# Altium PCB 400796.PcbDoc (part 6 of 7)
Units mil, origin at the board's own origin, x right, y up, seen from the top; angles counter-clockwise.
Board outline 2086.61 x 2086.61 mil, 6 copper layers (Top Layer, Mid Layer 1, Mid Layer 2, Mid Layer 3, Mid Layer 4, Bottom Layer), stack 58.818 mil thick; 313 components, 234 nets, 1244 pads, 2538 vias.
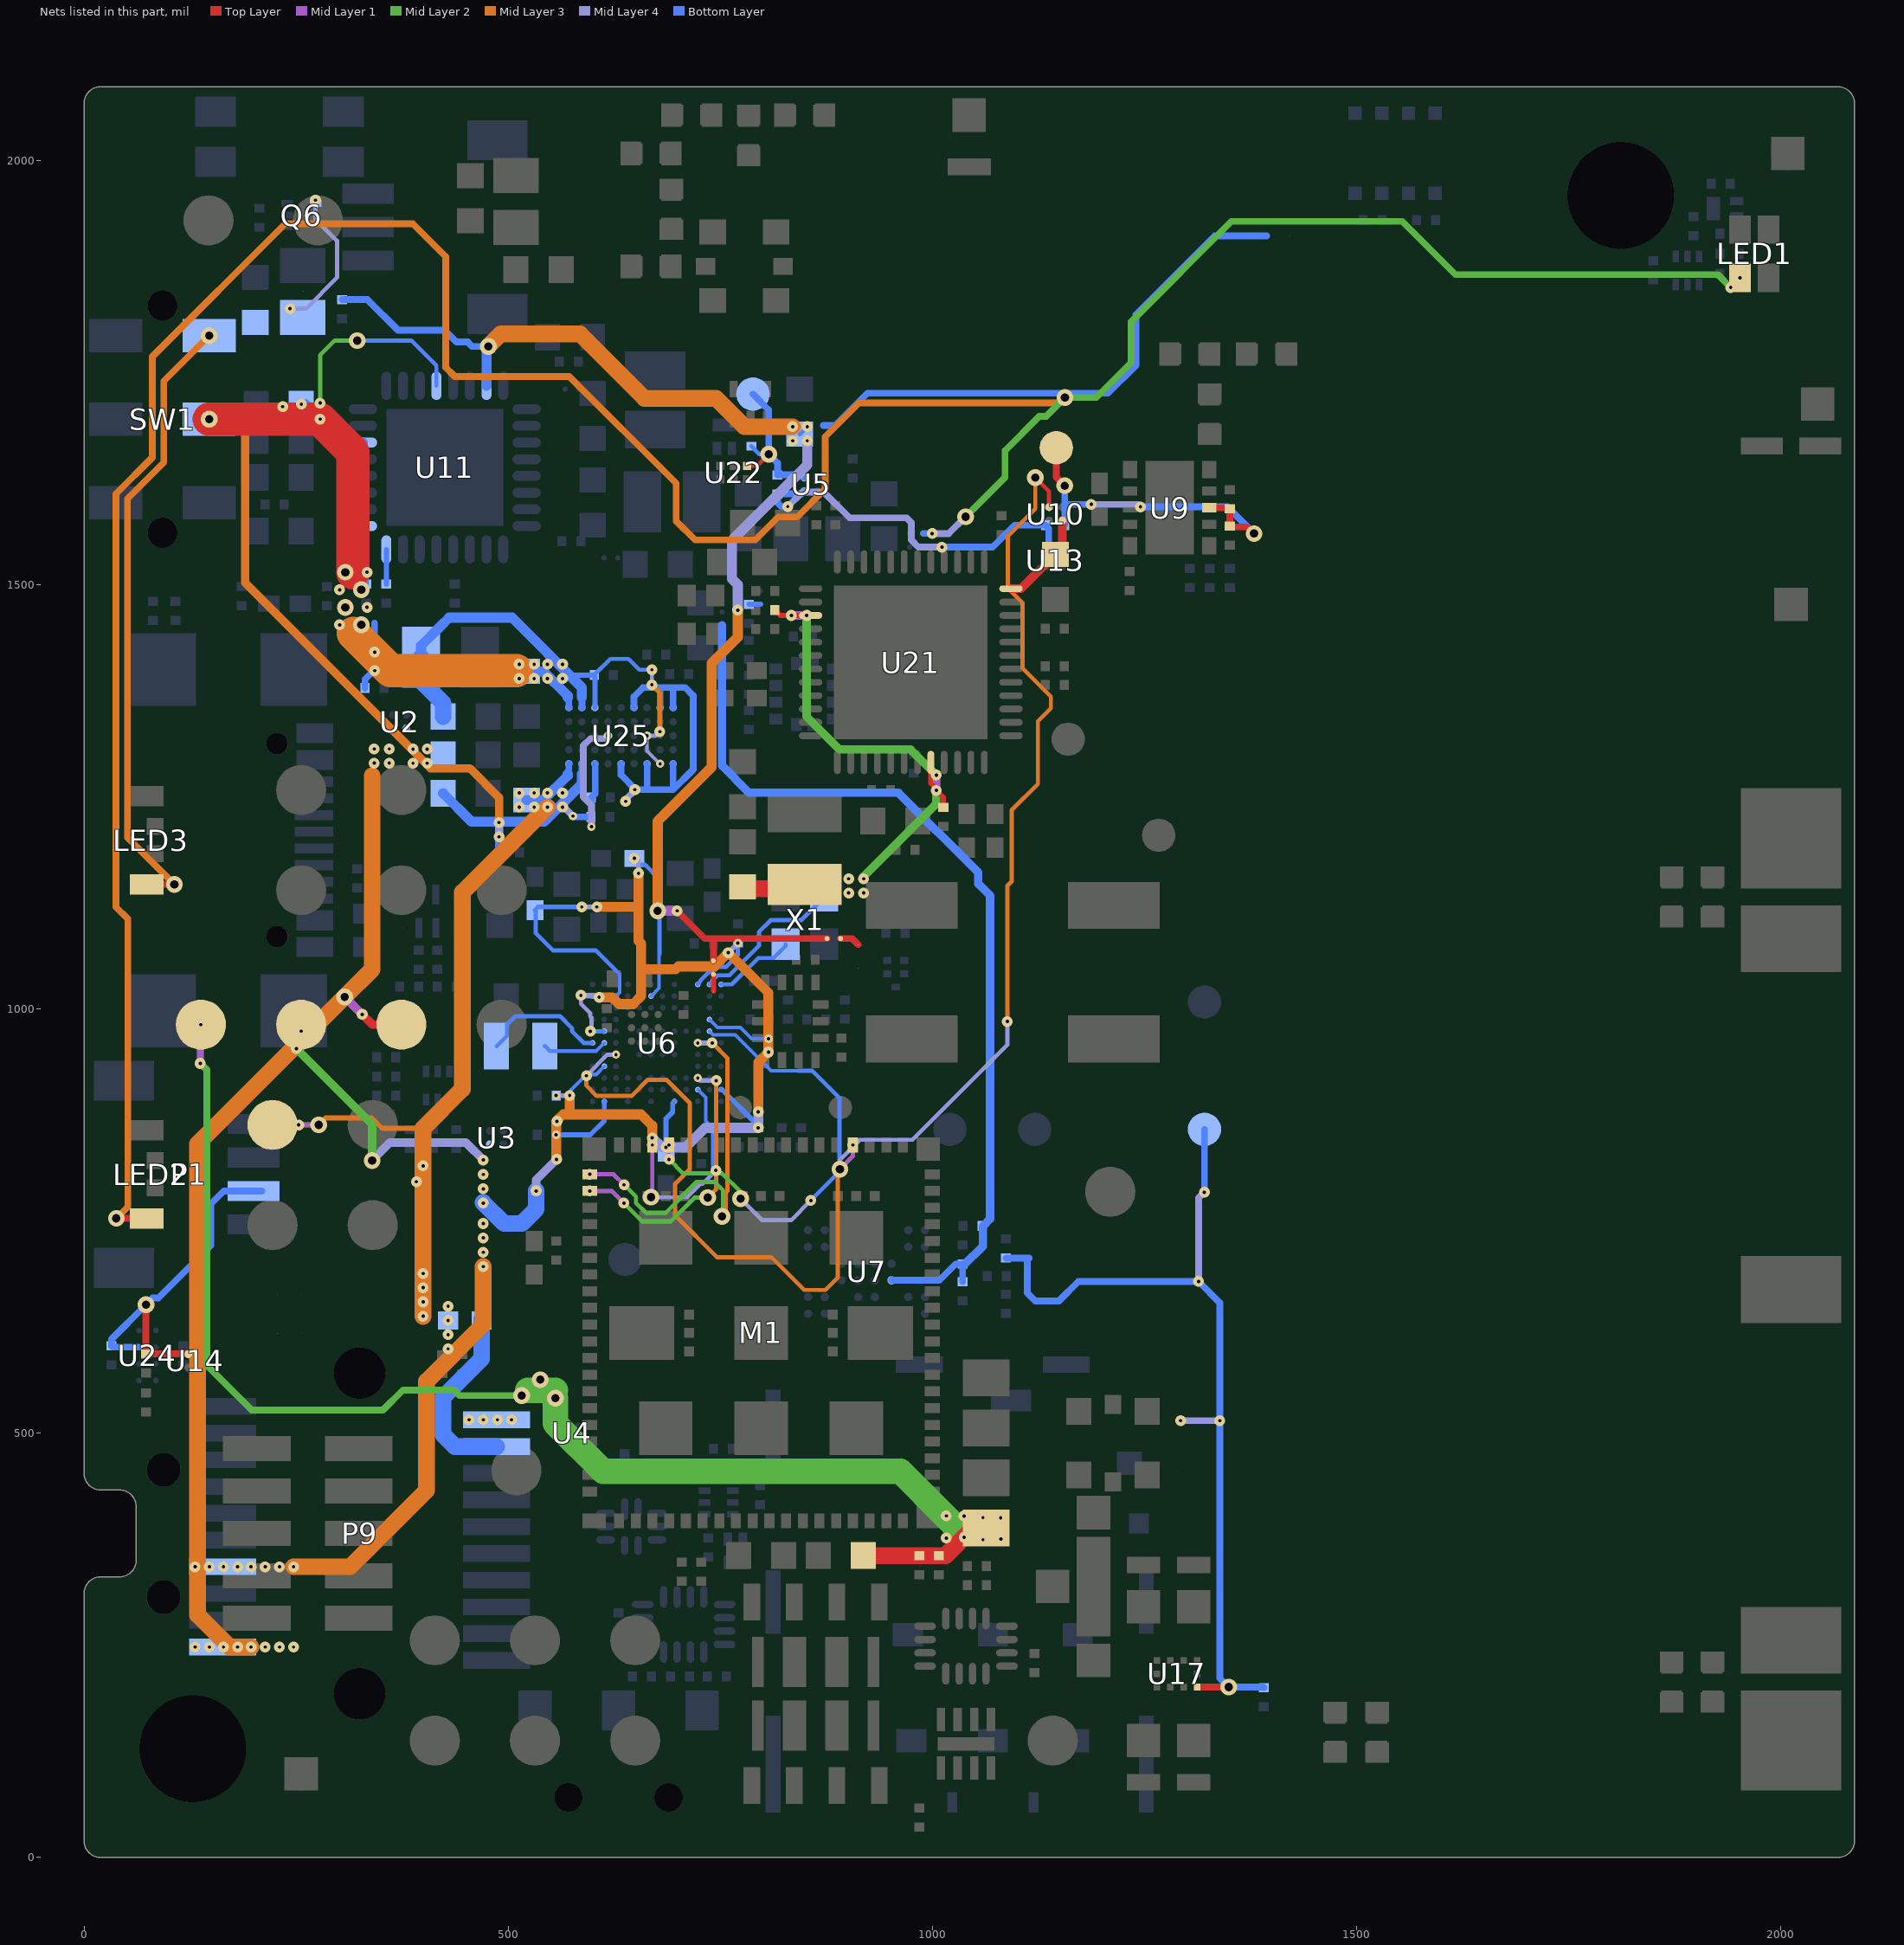
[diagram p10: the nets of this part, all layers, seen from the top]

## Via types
v1: diameter 12.8, hole 3.94, Mid Layer 4 to Bottom Layer, tented both sides, 653 vias
v2: diameter 12.8, hole 3.94, Top Layer to Mid Layer 1, tented both sides, 560 vias
v3: diameter 12.8, hole 3.94, Mid Layer 3 to Mid Layer 4, tented both sides, 388 vias
v4: diameter 19.68, hole 9.84, Mid Layer 1 to Mid Layer 4, tented both sides, 311 vias
v5: diameter 12.8, hole 3.94, Mid Layer 1 to Mid Layer 2, tented both sides, 265 vias
v6: diameter 19.68, hole 9.84, Top Layer to Bottom Layer, tented both sides, 169 vias
v7: diameter 9.84, hole 3.94, Mid Layer 4 to Bottom Layer, tented both sides, 105 vias
v8: diameter 12.8, hole 3.94, Top Layer to Mid Layer 1, tented top, 70 vias
v9: diameter 9.84, hole 3.94, Top Layer to Mid Layer 1, tented both sides, 17 vias

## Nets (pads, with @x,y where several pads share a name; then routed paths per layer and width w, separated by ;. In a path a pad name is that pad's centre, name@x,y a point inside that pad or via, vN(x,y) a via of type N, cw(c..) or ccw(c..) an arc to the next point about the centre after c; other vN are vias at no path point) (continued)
VBUSOUT: C50.2 R10.1 U11.22 | length 817.3
  Mid Layer 3 w9.84: v3@230.08,1709.58 214.8,1709.58 189.96,1684.75 189.96,1531.64 189.95,1501.98 408.46,1283.46 454.72,1283.46 489.17,1249.02 v3(489.17,1219.49)
  Mid Layer 4 w9.84: v3(234.08,1709.58) 253.14,1709.58 v1(256.16,1712.6) ; v1(489.17,1202.76) v3(489.17,1219.49)
  Bottom Layer w9.84: v1(489.17,1202.76) 489.17,1185.81 R10.1@490.73,1184.25
  Bottom Layer w11.81: v1(256.16,1712.6) 260.51,1712.6 282.44,1690.67 305.79,1667.32 U11.22@328.74,1667.32
VCOM0.RXD: M1.57 U6.K3 | length 261
  Mid Layer 1 w4.92: v4(668.34,778.09) 669.8,779.56 v2(669.8,839.57)
  Mid Layer 4 w4.92: v4@665.34,784.09 671.51,777.92 710.43,777.92 726.29,793.79 728.81,793.79 v1(744.68,809.66)
  Bottom Layer w4.13: U6.K3@723.41,904.72 732.87,895.26 732.87,867.69 741.56,859
  Bottom Layer w4.92: 741.56,859 741.56,812.78 v1(744.68,809.66)
VCOM0.TXD: M1.56 U6.E2 | length 549.9
  Mid Layer 1 w4.92: v5(689.49,822.64) v2(689.49,839.57)
  Mid Layer 2 w4.92: v5(689.49,822.64) 705.97,806.16 751.95,806.16 773.75,784.36 v4(773.75,776.36)
  Mid Layer 4 w4.92: v4(773.75,776.36) 799.13,750.98 833.46,750.98 v1(856.6,774.12) v1@857.6,775.12
  Bottom Layer w4.13: U6.E2@737.19,973.62 741.42,969.39 767.59,969.39 809.96,927.02 842,927.02
  Bottom Layer w4.92: 842,927.02 858.34,927.02 890.27,895.09 890.27,807.8 v1(856.6,774.12)
VCOM1.RXD: M1.62 U6.J3 | length 330.7
  Mid Layer 1 w4.92: v2(595.98,785.43) 621.98,785.43 v5(636.36,771.06)
  Mid Layer 2 w4.92: v5(636.36,771.06) 657.91,749.51 691.41,749.51 719.57,777.66 v4(735.14,777.66)
  Mid Layer 3 w4.92: v4(735.14,777.66) 745.16,787.68 745.16,859 v3(745.16,915.5)
  Mid Layer 4 w5.91: v7(723.41,918.5) 726.41,915.5 v3(745.16,915.5)
VCOM1.TXD: M1.61 U6.F3 | length 462
  Mid Layer 1 w4.92: v2(595.98,805.12) 624.11,805.12 v5(636.49,792.74)
  Mid Layer 2 w4.92: v5(636.49,792.74) 650.36,778.87 650.36,771.41 661.88,759.89 685.97,759.89 715.94,789.86 722.08,796 743.4,796 749.58,789.83 752.87,786.53 752.87,756.36 v4(751.83,755.32)
  Mid Layer 3 w5: v3(740.38,959.84) 758.21,942 758.21,785.44 756.48,783.7 756.48,759.97 v4(751.83,755.32)
  Mid Layer 4 w5.91: v7(723.41,959.84) v3(740.38,959.84)
VDD_ACC: R26.1 ST7.2 | length 13.9
  Bottom Layer w6: R26.1@783.46,1476.77 ST7.2@797.35,1476.77
VDD_BMI270: SB4.1 ST1.2 | length 23.6
  Top Layer w8: ST1.2@891.65,1082.91 905.13,1082.91 SB4.1@912.32,1075.72
VDD_BMM350: SB10.1 ST4.2 | length 19.9
  Top Layer w6: SB10.1@741.78,1020.8 ST4.2@741.78,1040.69
VDD_BUCK: C60.2 C65.2 C70.2 L6.2 U21.15 U21.32 | length 669.2
  Top Layer w6: C70.2@814.17,1469.99 814.17,1469.4 816.49,1467.09 817.08,1467.09 820.58,1463.58 v2(833.66,1463.58) U21.15@856.3,1463.58 ; U21.32@998.03,1290.35 998.03,1265.87 1004.45,1259.45 v2(1004.45,1257.48) 1012.8,1249.13 C60.2@1012.8,1237.6
  Top Layer w20: C65.2@780.7,1141.46 L6.2@824.47,1141.46 ; L6.2@829.72,1146.71 L6.2@824.47,1141.46 ; L6.2@844.16,1141.46 L6.2@824.47,1141.46
  Mid Layer 1 w9.84: v2(833.66,1463.58) v5(851.66,1463.58) ; v2(1004.45,1257.48) v5(1004.45,1275.48)
  Mid Layer 2 w9.84: v5(851.66,1463.58) 851.66,1344.32 890.28,1305.71 974.22,1305.71 v5(1004.45,1275.48) 1004.45,1241.73 918.82,1156.1 v5(918.82,1153.23)
  other v2: 901.1,1136.5 901.1,1153.23
  other v5: 918.82,1136.5
VDD_ENV: SB5.1 ST5.2 | length 650
  Bottom Layer w7.87: ST5.2@871.19,1687.36 885.19,1687.36 923.23,1725.39 1206.69,1725.39 1239.67,1758.37 1239.67,1817.96 1332.63,1910.93 SB5.1@1393.71,1910.93
VDD_EXP_BRD: C76.2 P1.2 R5.1 U14.A1 U24.B2 | length 424.5
  Top Layer w8: v6(72.97,651.36) R5.1@72.97,593.4 122.42,593.4 U14.A1@122.46,593.44
  Bottom Layer w8: U24.B2@64.96,601.38 33.86,601.38 C76.2@32.48,602.76 32.48,610.86 v6@71.44,649.83 ; v6(72.97,651.36) 80.76,659.15 87.51,659.15 149.67,721.31 149.67,770.16 164.94,785.43 P1.2@209.65,785.43
VDD_LED: LED1.4 LED2.4 ST2.2 | length 3781.9
  Top Layer w7.87: v6(38.09,753.11) LED2.4@73.74,753.12
  Mid Layer 1 w5.91: v5(1940.64,1850.08) v2(1951.77,1861.22)
  Mid Layer 2 w7.87: v4(1039.1,1579.89) 1085.48,1626.28 1085.48,1657.81 1125.8,1698.12 1133.75,1698.12 v4(1156.09,1720.46) 1192.95,1720.46 1233.82,1761.33 1233.82,1809.38 1352.31,1927.87 1553.74,1927.87 1616.53,1865.08 1925.64,1865.08 v5(1940.64,1850.08)
  Mid Layer 3 w7.87: v6(38.09,753.11) 51.7,766.71 51.7,1106.06 37.56,1120.2 37.56,1606.79 80.54,1649.77 80.54,1768.57 237.16,1925.2 387.45,1925.2 426.18,1886.46 426.18,1755.91 437.01,1745.08 571.98,1745.08 697.83,1619.22 697.83,1574.8 720.17,1552.47 791.1,1552.47 818.35,1579.73 840.64,1579.73 873.44,1612.52 873.44,1673.99 913.52,1714.07 1149.7,1714.07 v4(1156.09,1720.46)
  Mid Layer 4 w7.87: v1(999.6,1560.04) 1019.25,1560.04 v4(1039.1,1579.89)
  Bottom Layer w7.87: ST2.2@989.03,1560.17 999.47,1560.17 v1(999.6,1560.04)
VDD_MEM: C37.2 R43.2 R50.2 ST9.2 U7.C3 | length 1114
  Bottom Layer w7.87: U7.C3@951.77,680.12 1007.87,680.12 1027.16,699.41 C37.2@1035.43,699.41 R50.2@1035.43,678.54
  Bottom Layer w9.84: ST9.2@751.97,1451.77 ST9.2@751.97,1451.65 751.97,1286.42 783.73,1254.65 959.87,1254.65 1053.94,1160.59 1053.94,1147.43 1067.91,1133.45 1067.91,752.56 1059.45,744.09 1059.45,720.37 C37.2@1036.44,697.37
VDD_nRF53: C12.1 C13.1 C15.1 C16.1 C19.1 C20.1 C21.1 C22.2 P9.4 TP2.1 U3.A1 U6.A3 U6.B7 U6.B10 U6.B12 U6.D2 U6.E11 U6.H11 U6.K1 U6.L5 U6.L11 | length 2954.3
  Top Layer w5.91: v2(255.84,973.76) 255.91,973.82 TP2.1@255.91,981.39
  Mid Layer 1 w5.91: v5(250.31,953.22) 255.84,958.76 v2(255.84,973.76)
  Mid Layer 2 w10: v5(250.31,953.22) 339.54,864 v4(339.54,821.38)
  Mid Layer 3 w11.81: v3@556.48,823.04 556.48,867.52 564.55,875.59 656.39,875.59 669.61,862.37 v3(669.61,847.92) ; 572.42,875.98 v3(572.42,897.83) ; v3(604.33,1120.08) 653.53,1120.09 ; v3(607.08,1013.63) 622.45,1013.63 630.47,1005.61 647.07,1005.61 656.53,1015.06 656.53,1046.56 ; v3(653.53,1159.65) 653.53,1120.09 ; v3(794.64,878.78) 794.64,936.98 v3(806.68,949.02) 806.68,1018.87 v3(759.32,1066.23) 743.07,1049.98 700.47,1049.98 697.05,1046.56 656.53,1046.56 ; 653.53,1120.09 653.53,1080.03 656.53,1077.03 656.53,1046.56
  Mid Layer 3 w19.68: v3(247.05,342.52) 313.73,342.52 403.54,432.34 403.54,561.02 470.47,627.95 v3(470.47,696.25)
  Mid Layer 4 w4.92: v1(585.61,1015.95) 585.61,1005.9 596.71,994.8 596.71,991.62 597.24,991.09 597.24,990.8 597.55,990.49 597.55,989.21 598.08,988.69 598.08,974.9 v1(596.79,973.62)
  Mid Layer 4 w5.91: v7(556.48,851.58) v3@556.48,867.32 ; v7(556.48,897.83) v3@572.23,897.83 ; v1(585.61,1015.95) 604.77,1015.95 v3(607.08,1013.63) ; v1(586.61,1120.08) v3(604.33,1120.08) ; v3(653.53,1159.65) v1@653.53,1175.39 ; v3@759.52,1066.42 v7(770.65,1077.56) ; v3(806.68,949.02) v7(806.68,964.76)
  Mid Layer 4 w10: v4(339.54,821.38) 360.5,842.34 449.98,842.34 v1(470.47,821.85) ; v1(532.84,785.4) 532.84,798.61 546.08,811.84 v3(556.88,822.64)
  Mid Layer 4 w11.81: v3(669.61,847.92) 669.97,847.92 681.01,836.89 v1(686.01,836.89)
  Mid Layer 4 w12: v1(686.01,836.89) 709.3,836.89 732.25,859.84 v1(794.64,859.84) v3(794.64,878.78)
  Bottom Layer w4.13: C20.1@557,897.83 567.31,897.83 592.01,922.54 599.19,922.54 599.39,922.74 603.62,922.74 U6.H11@613.17,932.28 ; 626.76,1045.28 631.18,1040.85 631.18,1019.19 U6.B10@626.95,1014.96 ; U6.B7@668.29,1014.96 677.84,1024.51 677.84,1064.94 ; U6.D2@737.19,987.4 746.73,977.85 773.6,977.85 786.62,964.84 C12.1@805.96,964.84
  Bottom Layer w4.92: C22.2@531.48,1116.34 C22.2@535.22,1120.08 ; C22.2@532.46,1116.34 532.46,1089.17 552.71,1068.92 603.12,1068.92 626.76,1045.28 ; v7(556.48,897.83) C20.1@557,897.83 ; v1(596.79,973.62) U6.E11@613.17,973.62 ; v1(648.6,1177.36) 655.99,1169.98 660.91,1169.98 678.13,1152.76 678.13,1063.98 ; U6.A3@723.41,1028.74 723.41,1029.22 726.46,1032.27 726.46,1033.32 742.45,1049.31 756.61,1049.31 770.65,1063.35 C21.1@770.65,1073.62
  Bottom Layer w5.91: C22.2@535.22,1120.08 v1(586.61,1120.08) ; v7(556.48,851.58) 596.74,851.58 613.17,868 U6.L11@613.17,890.95 ; v1(585.61,1015.95) 586.6,1014.96 U6.B12@599.39,1014.96 ; v1(686.01,836.89) 686.01,870.63 693.82,878.44 693.82,888.92 U6.L5@695.85,890.95 ; U6.K1@750.97,904.72 751.12,904.57 752.09,904.57 C13.1@794.64,862.03
  Bottom Layer w19.68: v1@470.47,771.65 495.08,747.04 515.92,747.04 532.84,763.97 v1(532.84,785.4)
  other v1: 130.9,342.52 147.64,342.52 164.37,342.52 181.1,342.52 470.47,771.06 470.47,787.99 470.47,804.92
  other v3: 196.85,342.52 213.58,342.52 230.32,342.52 470.47,713.18 470.47,730.11 470.47,747.04 557.48,867.52
VDD_nRF91: C1.1 C2.1 C3.1 FB1.1 P9.11 TP3.1 U4.A1 | length 1555.2
  Top Layer w20: FB1.1@918.57,355.52 C2.1@1007.35,355.52 ; C2.1@1007.22,355.62 1015.38,355.62 1048.16,388.4 C3.1@1063.24,388.4
  Mid Layer 1 w8: v5(137.07,935.72) 137.07,980.66 v2(137.8,981.39)
  Mid Layer 2 w8: v5(137.07,935.72) 144.7,928.08 144.7,579.98 197.49,527.19 352.36,527.19 376.02,550.84 435.78,550.84 442.28,544.34 v4(515.7,544.34)
  Mid Layer 2 w30: v4@522.95,550.34 v4@555.47,550.34 ; v4(555.47,541.34) 555.47,511.53 611.94,455.06 962.06,455.06 1015.44,401.68 1028.71,388.41
  other v1: 453.74,515.75 470.47,515.75 487.21,515.75 503.94,515.75
  other v2: 1059.47,374.43 1080.55,375.35 1059.47,400.55 1080.39,400.42
  other v4: 537.59,563.02
  other v5: 1016.26,376.37 1037.34,377.29 1016.26,402.49 1037.18,402.36
VDD_nRF91_RES: P9.12 R24.1 U4.A2 | length 223.8
  Bottom Layer w19.68: R24.1@468.51,634.37 468.51,587.6 423.23,542.32 423.23,498.03 437.01,484.25 P9.12@486.22,484.25
VDD_RF_FE_3V3: C32.2 C33.2 R56.1 TP8.1 U9.3 U13.A1 | length 428.2
  Top Layer w7.87: TP8.1@1145.87,1661.19 1145.87,1626.52 v6(1155.91,1616.49) ; U9.3@1326.28,1590.55 1343.81,1590.55 ; C32.2@1350.39,1583.97 1350.39,1567.91 1371.06,1567.91 v6(1378.94,1560.04)
  Mid Layer 4 w7.87: v1(1187.01,1594.49) 1242.13,1594.49 v1(1245.08,1591.54)
  Bottom Layer w7.87: U13.A1@1152.56,1536.55 R56.1@1152.56,1566.66 ; R56.1@1155.91,1570.01 1155.91,1594.49 ; v6(1155.91,1616.49) 1155.91,1594.49 ; v1(1187.01,1594.49) 1155.91,1594.49 ; v1(1245.08,1591.54) 1347.44,1591.54 v6(1378.94,1560.04)
VDD_RF_FE_3V3_SP: R25.2 R56.2 ST3.2 U5.A2 U13.A2 | length 474.7
  Mid Layer 4 w7.87: v1(829.47,1591.77) 846.68,1608.97 871.87,1608.97 902.27,1578.58 969.45,1578.58 975.03,1573 975.03,1552.48 983.44,1544.07 v1(1011.13,1544.07)
  Bottom Layer w7.87: v1(829.47,1591.77) 822.03,1591.77 817.36,1596.43 R25.2@817.36,1606.83 845.51,1606.83 U5.A2@848.86,1610.18 ; ST3.2@989.03,1544.07 v1(1011.13,1544.07) 1070.64,1544.07 1096.58,1570.01 R56.2@1133.46,1570.01 ; R56.2@1133.17,1570.01 R56.2@1133.32,1569.87 ; R56.2@1133.46,1569.42 1136.81,1566.07 U13.A2@1136.81,1536.55
VDD_RF_FE_SR: R25.1 R62.1 TP11.1 U5.A1 U22.4 | length 195.9
  Top Layer w4.92: U22.4@781.5,1639.76 793.31,1639.76 v6(807.09,1653.54)
  Bottom Layer w4.92: R62.1@786.42,1662.99 795.87,1653.54 v6(807.09,1653.54)
  Bottom Layer w7.87: TP11.1@788.39,1724.41 807.09,1705.71 v6(807.09,1653.54) 817.36,1643.27 R25.1@817.36,1629.27 845.51,1629.27 U5.A1@848.86,1625.93
VDD_SENS: C90.2 R30.2 ST1.1 ST4.1 ST5.1 U11.31 | length 1556
  Top Layer w8: v2(698.94,1115.44) 731.47,1082.91 741.96,1082.91 ; ST4.1@741.78,1056.69 741.78,1082.74 741.96,1082.91 ; ST1.1@875.65,1082.91 741.96,1082.91
  Mid Layer 1 w12: v4(676.08,1115.44) v2(698.94,1115.44)
  Mid Layer 3 w12: v4(676.08,1115.44) 676.08,1221.09 739.66,1284.67 739.66,1407.26 770.44,1438.04 v3(770.44,1469.78)
  Mid Layer 3 w19.68: v6(476.38,1780.51) 491.14,1795.28 584.65,1795.28 660.59,1719.33 745.01,1719.33 778.32,1686.02 v3(835.17,1686.02)
  Mid Layer 4 w4.92: v1(835.17,1669.29) v3(835.17,1686.02)
  Mid Layer 4 w12: v3(770.44,1469.78) 770.44,1499.9 763.68,1506.66 763.68,1552.02 852.36,1640.7 v1(852.36,1669.29)
  Bottom Layer w4.92: C90.2@843.5,1677.17 853.69,1687.36 ST5.1@855.19,1687.36
  Bottom Layer w8: R30.2@304.16,1835.77 334.06,1835.77 370.13,1799.7 424.99,1799.7 438.95,1785.73 452.26,1785.73 457.48,1780.51 v6@474.41,1780.51
  Bottom Layer w11.81: U11.31@474.41,1734.25 474.41,1780.51 v6(476.38,1780.51)
  other v3: 852.36,1686.02
VDDIO_CTRL: M1.45 U6.G10 U10.B2 | length 1770.2
  Top Layer w4.92: v6(1121.06,1625.98) 1137.32,1609.72 U10.B2@1137.32,1591.14
  Mid Layer 1 w4.92: v4(890.91,811.19) 906.02,826.31 v2(906.02,839.57)
  Mid Layer 3 w4.92: v3(592.08,921.24) 592.08,909.59 604.21,897.45 645.43,897.45 664.36,916.38 686.66,916.38 713.93,889.11 713.93,810.93 696.58,793.58 696.58,756.76 746.16,707.18 810.49,707.18 848.91,668.76 873.87,668.76 888.45,683.34 888.45,808.74 v4(890.91,811.19) ; v3(1088.08,985.15) 1088.08,1144.86 1093.34,1150.11 1093.34,1234.23 1124.21,1265.1 1124.21,1338.99 1139.45,1354.22 1139.45,1367.83 1106.19,1401.09 1106.19,1478.25 1088.86,1495.59 1088.86,1557.28 1121.06,1589.48 v6(1121.06,1625.98)
  Mid Layer 4 w4.92: v3(592.08,921.24) 616.9,946.06 v7(626.95,946.06) ; v4(890.91,811.19) 890.91,822.33 914.37,845.78 976.51,845.78 1088.08,957.36 v3(1088.08,985.15)
VDDIO_nRF70: C30.2 U10.A1 U21.48 | length 111.9
  Top Layer w10: U21.48@1092.52,1495.08 1104.33,1495.08 C30.2@1144.68,1535.43 C30.2@1152.09,1542.83 ; C30.2@1153.07,1542.83 U10.A1@1153.07,1575.39
VIO: C38.2 R29.2 SB1.1 TP21.1 U17.4 | length 1080.7
  Top Layer w7.87: U17.4@1311.75,200.77 v6(1349.15,200.77)
  Mid Layer 4 w7.87: v1(1292.32,514.76) v1(1338.58,514.76) ; v1@1313.55,679.76 1313.55,777.1 v1(1320.36,783.91)
  Bottom Layer w7.87: R29.2@1086.61,706.3 1113.91,706.3 ; 1111.71,704.11 1111.71,665.16 1121.12,655.76 1148.95,655.76 1171.95,678.76 v1(1313.55,678.76) 1338.58,653.73 v1(1338.58,514.76) 1338.58,211.34 v6(1349.15,200.77) 1389.97,200.77 C38.2@1390.57,200.18 ; v1(1320.36,783.91) 1320.47,784.02 TP21.1@1320.47,858.07
VOUT_BUCK0: C78.2 C82.1 L9.2 U25.B1 U25.C3 U25.G5 U25.H5 | length 634
  Mid Layer 3 w5.91: v3(669.29,1381.89) 678.6,1372.58 v3(678.6,1326.59)
  Mid Layer 4 w4.13: v7(663.58,1321.85) 663.58,1304.13 v7(678.94,1288.78)
  Mid Layer 4 w4.92: v7(663.58,1321.85) 673.87,1321.85 v3(678.6,1326.59) ; v3(669.29,1381.89) v1(669.29,1399.61)
  Bottom Layer w4.92: C82.1@599.41,1393.31 601.23,1393.31 620.32,1412.4 641.73,1412.4 654.53,1399.61 v1(669.29,1399.61)
  Bottom Layer w5.91: 573.22,1393.31 C82.1@599.41,1393.31 ; U25.G5@602.17,1354.92 C82.1@602.17,1390.98
  Bottom Layer w7.87: U25.H5@586.81,1354.92 586.81,1366.93
  Bottom Layer w11.81: L9.2@397.24,1414.37 397.24,1427.95 419.49,1450.2 430.32,1461.02 504.53,1461.02 586.81,1378.74 586.81,1366.93
  Bottom Layer w19.68: L9.2@397.24,1414.37 397.24,1386.22 423.23,1360.24 C78.2@423.23,1344.49
VOUT_BUCK3: C81.2 L10.2 P9.1 TP14.1 U2.A2 U25.H1 | length 1452.8
  Top Layer w10: v2(327.86,993.41) 328.04,993.41 340.06,981.39 TP14.1@374.02,981.39
  Mid Layer 1 w10: v4(307.05,1014) 307.27,1014 v2(327.86,993.41)
  Mid Layer 3 w19.68: v3(196.85,248.03) 171.71,248.03 133.86,285.89 133.86,840.8 v4(307.05,1014) 339.57,1046.51 339.57,1274.61
  Bottom Layer w7.87: 586.81,1276.77 U25.H1@586.81,1288.78
  Bottom Layer w11.81: L10.2@423.23,1253.94 456.69,1220.47 542.32,1220.47 586.81,1264.96 586.81,1276.77
  other v1: 130.9,248.03 147.64,248.03 164.37,248.03 181.1,248.03 387.79,1289.37 404.52,1289.37 387.79,1306.1 404.52,1306.1
  other v3: 213.58,248.03 230.32,248.03 247.05,248.03 342.06,1289.57 359.78,1289.57 342.06,1306.3 359.78,1306.3
VSET1: R7.1 U11.17 | length 76.7
  Bottom Layer w5.91: U11.17@318.9,1566.17 321.63,1568.9 U11.17@328.74,1568.9 ; R7.1@332.68,1500.39 U11.17@332.68,1566.17
VSET2: R8.1 U11.16 | length 40.9
  Bottom Layer w5.91: R8.1@356.3,1500.39 U11.16@356.3,1541.34
VSYS: C98.2 FB5.2 LED3.4 Q6.4 SW1.6 | length 914.9
  Top Layer w7.87: LED3.4@73.74,1146.82 106.26,1146.82 v6(106.49,1146.59)
  Mid Layer 3 w7.87: v6(106.49,1146.59) 51.13,1201.95 51.13,1601.14 94,1644.02 94,1739.67 v6(147.64,1793.31)
  Mid Layer 4 w4.92: v1(242.72,1825.07) 261.68,1825.07 298.15,1861.54 298.15,1905.11 272.78,1930.47 v1(272.78,1952.93)
VSYS_SW: C77.2 C80.2 C83.1 C84.1 R3.2 R24.2 SW1.5 TP17.1 U11.28 U25.A1 U25.A5 U25.B5 U25.C1 U25.D5 U25.E1 U25.F3 U25.G1 U25.J1 U25.J5 | length 2582.2
  Top Layer w6: TP17.1@222.15,863.28 v2(253.05,863.28)
  Top Layer w39.37: v6(147.64,1694.88) v2(278.23,1694.88) 316.93,1656.18 316.93,1513.78
  Mid Layer 1 w4.92: v2(278.23,1694.88) v5(278.23,1713.9)
  Mid Layer 1 w6: v2(253.05,863.28) v4(276.63,863.28)
  Mid Layer 2 w4.92: v5(278.23,1713.9) 278.23,1770.15 295.54,1787.46 v6(321.87,1787.46)
  Mid Layer 3 w6: v4@274.63,863.28 v4@275.63,864.28 ; v4(276.63,863.28) 284.8,871.45 339.18,871.45 351.38,859.25 399.61,859.25
  Mid Layer 3 w11.81: 399.54,783.46 399.61,783.39
  Mid Layer 3 w19.68: v3(399.61,637.8) v3(399.61,654.73) v3(399.61,671.46) v3(399.61,688.19) 399.61,783.39 399.61,859.25 445.87,905.51 445.87,996.03 445.87,1137.3 v3(546.26,1237.7)
  Mid Layer 3 w39.37: 317.42,1442.42 361.22,1398.62 509.84,1398.62
  Mid Layer 4 w7.87: v3(342.52,1398.62) v1(342.52,1420.28) ; v3(563.98,1237.7) 565.72,1237.7 v7(576.24,1227.18) ; v7(598.03,1214.59) 598.03,1240.21 588.39,1249.86 588.39,1310.02 596.86,1318.5 614.17,1318.5 v7(617.52,1321.85) ; v3@638.34,1246.57 v1@650.12,1258.35
  Mid Layer 4 w11.81: v1(391.73,796.26) 399.61,804.14 v3(399.61,814.96)
  Bottom Layer w4.92: v6(321.87,1787.46) 385.76,1787.46 415.35,1757.87 U11.28@415.35,1734.25
  Bottom Layer w7.87: R3.2@331.3,1377.95 331.3,1388.39 342.52,1399.61 v1(342.52,1420.28) 342.52,1454.72 ; 571.46,1276.77 U25.J1@571.46,1288.78 ; U25.J5@571.46,1354.92 571.46,1366.93 ; v7(576.24,1227.18) 577.23,1226.19 C83.1@597.5,1226.19 C83.1@598.03,1225.67 ; v7(598.03,1214.59) C83.1@598.03,1225.67 ; U25.G1@602.17,1288.78 602.32,1288.63 602.32,1288.07 602.56,1287.83 602.56,1253.54 C84.1@598.03,1249.02 598.03,1226.19 C83.1@598.03,1225.67 ; U25.E1@632.87,1288.78 632.87,1275.59 650.12,1258.35 663.58,1258.35 ; U25.D5@648.23,1354.92 648.23,1367.85 658.92,1378.54 678.94,1378.54 ; 663.58,1258.41 U25.C1@663.58,1288.78 ; 663.64,1258.35 694.29,1258.35 ; U25.B5@678.94,1354.92 678.94,1378.54 ; U25.A1@694.29,1288.78 694.29,1265.16 694.29,1258.37 ; U25.A5@694.29,1354.92 694.29,1378.54 ; 678.94,1378.54 694.29,1378.54 ; 694.32,1258.35 717.97,1282.01 717.97,1291.94 717.97,1369.13 708.56,1378.54 694.29,1378.54
  Bottom Layer w11.81: C80.2@521.65,1246.06 541.34,1246.06 570.08,1274.8 570.08,1276.77 ; C77.2@521.65,1397.64 541.34,1397.64 570.08,1368.9 570.08,1366.93
  other v1: 429.14,599.41 429.14,616.14 429.14,632.87 429.14,649.61 512.79,1237.7 530.51,1237.7 512.79,1254.43 530.51,1254.43 649.12,1258.35 512.79,1389.27 530.51,1389.27 512.79,1406 530.51,1406
  other v2: 301.26,1452.48 333.59,1473.15 301.26,1493.82 333.59,1514.49
  other v3: 638.34,1244.57 546.26,1254.43 563.98,1254.43 546.26,1389.27 563.98,1389.27 546.26,1406 563.98,1406
  other v4: 326.85,1452.48 307.99,1473.15 326.85,1493.82 307.99,1514.49
XC1: U6.A1 X1.1 | length 96.8
  Bottom Layer w4.92: U6.A1@750.97,1028.74 763.36,1028.74 794.57,1059.95 812.69,1059.95 826.96,1074.22 X1.1@826.96,1076.19
XC2: U6.A2 X1.3 | length 189.9
  Bottom Layer w4.92: U6.A2@737.19,1028.74 737.19,1029.22 740.24,1032.27 740.24,1033.18 746.52,1039.47 760.69,1039.47 795.47,1074.25 795.47,1090.58 809.42,1104.53 845.45,1104.53 872.23,1131.31 X1.3@872.23,1133.28
XL1: U6.F11 X2.1 | length 76.5
  Bottom Layer w4.13: X2.1@557,950.3 603.62,950.3 U6.F11@613.17,959.84
  Bottom Layer w4.92: X2.1@543.09,956.3 549.1,950.3 X2.1@557,950.3
XL2: U6.F12 X2.2 | length 150.6
  Bottom Layer w4.92: X2.2@486.2,955.91 498.51,968.21 498.51,981.25 508.59,991.34 561,991.34 575.11,977.24 575.11,973.68 588.94,959.84 U6.F12@599.39,959.84
pads on no net: A1.0 A2.1 A2.2 A2.3 A3.0 D3. D3.4 Fid1.0 Fid2.0 H1. H2. J3.0 J4.C6 J6.0 J6.A8 J6.B8 M1.21 M1.22 M1.23 M1.26 M1.31 M1.32 M1.33 M1.37 M1.81 M1.82 M1.83 M1.84 M1.85 M1.86 M1.87 M1.88 M1.89 M1.90 M1.91 M1.92 M1.93 M1.94 M1.95 M1.96 M1.97 M1.98 M1.99 M1.100 M1.101 M1.102 M1.103 M1.104 P1.0 P8.0 P8.6 P8.7 P8.8 P9. P9.5 P9.6 P9.7 P9.13 SW1.0 SW2.0 U1.7 U1.8 U1.9 U1.10 U6.C7 U6.C9 U6.D11 U6.H2 U6.H12 U6.J4 U6.J5 U6.J6 U6.K8 U6.K10 U7.A1 U7.A5 U7.A6 U7.B1 U7.B2 U7.B5 U7.B6 U7.D1 U7.D2 U7.D6 U7.E1 U7.E2 U7.E5 U7.E6 U7.G1 U7.G2 U7.G5 U7.G6 U7.H1 U7.H2 U7.H5 U7.H6 U8.4 U9. U12.9 U15.0 U15.2 U15.4 U15.5 U16.10 U18.9 U18.10 U18.11 U20.6 U20.8 U21.2 U21.3 U21.4 U21.5 U21.6 U21.21 U21.22 U21.23 U21.24 U21.39 U21.40 U25.A2 U25.A4 U25.B4 U25.C5 U25.D1 U25.D4 U25.E4

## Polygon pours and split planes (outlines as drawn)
GND on Mid Layer 3 "Mid_Layer_3-GND" (solid, remove dead copper, pour order 114): 2086.61,0 0,0 0,2086.61 2086.61,2086.61
VSYS_SW on Mid Layer 3 "Mid_Layer_2-Vin" (solid, pour order 14): 620.08,1295.28 666.34,1249.02 666.34,1229.35 534.9,1229.35 534.9,1418.31 620.08,1418.31
GND on Bottom Layer "Bottom_Layer-GND" (solid, remove dead copper, pour order 116): 2086.61,0 0,0 0,2086.61 2086.61,2086.61
Shield on Bottom Layer "SHIELD_L06_P115" (solid, pour order 115): -0.25,1464.96 132.73,1464.96 132.73,1442.91 286.61,1442.91 286.61,1344.13 212.46,1344.13 212.46,1051.02 286.61,1051.02 286.61,954.72 0,954.72 0,992.74
GND on Mid Layer 4 "Mid_Layer_4-GND" (solid, remove dead copper, pour order 111): 2086.61,0 0,0 0,2086.61 2086.61,2086.61
GND on Mid Layer 2 "Mid_Layer_2-GND" (solid, remove dead copper, pour order 110): 2086.61,0 0,0 0,2086.61 2086.61,2086.61
GND on Top Layer "Top_Layer-GND" (solid, remove dead copper, pour order 10): 2086.61,0 0,0 0,2086.61 2086.61,2086.61
GND on Mid Layer 1 "Mid_Layer_1-GND" (solid, remove dead copper, pour order 12): 2086.61,0 0,0 0,2086.61 2086.61,2086.61

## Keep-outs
Top Layer:
  rectangle: -6.79,1014.37 44.83,1073.63
Mid Layer 1:
  region: 1206.48,212.07 1206.48,217.35 cw(c1263.62,217.35) 1223.22,257.76 ccw(c1185.16,295.81) 1238.98,295.81 1238.98,301.06 1183.83,301.06 1183.83,212.07
  region: 1312.35,162.33 1281.72,199.8 1262.56,199.8 1231.92,162.35
  region: 1312.32,270.71 1281.72,233.27 1262.47,233.27 1231.85,270.69
  region: 1513.78,138.78 1243.7,138.78 1243.7,38.39 1513.78,38.39
  region: 1513.78,394.68 1263.58,394.68 1263.58,294.29 1513.78,294.29
  region: 1399.41,141.84 1399.41,394.68 1504.06,394.68 1504.06,141.84
  region: 1478.94,197.33 1439.6,197.33 1439.6,335.13 1252.36,335.13 1252.36,353.82 1458.29,353.82 1458.29,216.02 1556.71,216.02 1556.71,157.96 1478.94,157.96
  region: 1391.34,78.74 1755.75,78.74 1755.75,97.91 1391.34,97.91
  lines w11.42: 692.19,1874.93 732.58,1874.93 ; 711.61,1216.54 689.05,1216.54 cw(c689.05,1261.74) 643.84,1261.74 643.84,1577.85 cw(c690.01,1577.85) 690.01,1624.02 738.45,1624.02 ; 765.75,1641.02 765.75,1698.82 ; 785.43,1730.31 785.43,1747.09 cw(c827.73,1747.09) 797.82,1776.99 798.25,1777.42 cw(c818.88,1756.78) 818.88,1785.97 ccw(c818.88,1809.4) 835.45,1792.83 836.78,1794.16 ccw(c803.96,1826.99) 850.38,1826.99 850.38,1858.31 ccw(c833.59,1858.31) 845.46,1870.18 ccw(c833.99,1858.71) 833.99,1874.93 823.92,1874.93 ; 793.1,1624.02 899.61,1624.02 cw(c899.61,1588.58) 935.04,1588.58 935.04,1549.21 ; 806.1,1694.88 918.28,1694.88 cw(c918.28,1646.63) 966.54,1646.63 966.54,1549.21
  lines w25.12: 965.08,869.54 965.08,866.12 cw(c1001.4,866.12) 975.72,891.81 cw(c998.71,868.82) 998.71,901.33 1261.27,901.33 ccw(c1261.27,990.9) 1324.61,927.57 ccw(c1262.78,989.39) 1350.22,989.39 1350.22,1245.98 ccw(c1250.22,1245.98) 1320.93,1316.69 1261.4,1376.22 cw(c1332.11,1446.93) 1232.11,1446.93 1232.11,1487.4 ; 1026.01,706.64 1078.2,706.64 cw(c1078.2,606.64) 1148.91,677.35 1183.31,642.96 cw(c1112.6,572.24) 1212.6,572.24 1212.6,533.86 ; 1189.72,405.31 1203.3,418.89 ccw(c1180.85,441.34) 1212.6,441.34 ; 1232.28,1487.4 1232.28,1446.93 ccw(c1332.28,1446.93) 1261.57,1376.22 1321.1,1316.69 cw(c1250.39,1245.98) 1350.39,1245.98 ; 1232.78,1520.67 1232.78,1545.53 ; 1326.28,1635.57 1326.28,1676.28 ; 1326.77,1724.8 1326.77,1771.26 ; 1327.17,1771.65 1369.68,1771.65
  lines w27.17: 785.43,2053.15 978.35,2053.15
Mid Layer 2:
  lines w44.88: 785.43,2053.15 978.35,2053.15
Mid Layer 4:
  lines w11.42: 711.61,1216.54 749.02,1216.54 931.09,1216.54 cw(c931.09,1181.1) 966.53,1181.1 966.53,1059.13 ; 875.24,987.41 933.23,987.41 ccw(c933.22,1010.85) 956.67,1010.85 956.67,1025.61
Bottom Layer:
  rectangle: 1379.78,932.89 1510.33,1153.72
  rectangle: -9.34,1917.84 126.77,1977.11
Keep-Out Layer:
  circle w6: c1263.78,2086.61 r6.81
  circle w6: c1232.28,2086.61 r6.81
  circle w6: c1200.79,2086.61 r6.81
  circle w6: c1169.29,2086.61 r6.81
  circle w6: c1137.8,2086.61 r6.81
  circle w6: c1137.8,0 r6.81
  circle w6: c1169.29,0 r6.81
  circle w6: c1200.79,0 r6.81
  circle w6: c1232.28,0 r6.81
  circle w6: c1263.78,0 r6.81
  circle w6: c2086.61,220.47 r6.81
  circle w6: c2086.61,188.98 r6.81
  circle w6: c2086.61,157.48 r6.81
  circle w6: c2086.61,125.98 r6.81
  circle w6: c2086.61,94.49 r6.81
  circle w6: c2086.61,1897.64 r6.81
  circle w6: c2086.61,1866.14 r6.81
  circle w6: c2086.61,220.47 r6.81
  circle w6: c2086.61,188.98 r6.81
  circle w6: c2086.61,157.48 r6.81
  circle w6: c2086.61,125.98 r6.81
  circle w6: c2086.61,94.49 r6.81
  circle w6: c0,220.47 r6.81
  circle w6: c0,188.98 r6.81
  circle w6: c0,157.48 r6.81
  circle w6: c0,125.98 r6.81
  circle w6: c0,94.49 r6.81
  circle w6: c0,1992.13 r6.81
  circle w6: c0,1960.63 r6.81
  circle w6: c0,1929.13 r6.81
  circle w6: c0,1897.64 r6.81
  circle w6: c0,1866.14 r6.81
  circle w6: c2086.61,1992.13 r6.81
  circle w6: c2086.61,1960.63 r6.81
  circle w6: c2086.61,1929.13 r6.81
  circle w6: c2086.61,1897.64 r6.81
  circle w6: c2086.61,1866.14 r6.81

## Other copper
Top Layer:
  rectangle net 1V8_SW: 519.38,713.21 541.12,743.25
  rectangle net NetA3_1: 874.02,2043.31 1043.31,2062.99
  rectangle net NetA1_1: 1460.7,94.49 1539.44,137.86
  region net VSYS_SW: 294.78,1525.32 294.78,1444.61 340.06,1444.61 340.06,1525.32
  region net NetJ1_1: 993.8,712.6 1010.29,712.6 ccw(c1010.29,722.68) 1017.42,715.55 1017.42,697.84 ccw(c1010.29,690.71) 1010.29,700.79 993.8,700.79
  region net GPS_RF1: 959.35,833.66 959.35,850.15 ccw(c949.27,850.15) 956.39,857.28 974.11,857.28 ccw(c981.24,850.15) 971.16,850.15 971.16,833.66
  region net NetJ1_3: 1222.44,453.94 cw(c1215.89,447.39) 1225.15,447.39 1225.15,441.34 1212.6,441.34 1212.6,453.94
  region net NetJ1_3: 1202.76,453.94 ccw(c1209.3,447.39) 1200.04,447.39 1200.04,441.34 1212.6,441.34 1212.6,453.94
  pour cut-out: 874.36,1317.8 883.22,1317.8 960.98,1317.8 960.98,1186.5 cw(c865.12,1177.39) 939.32,1116.03 cw(c905.02,1144.94) 908.81,1100.24 777.76,1100.24 cw(c782.17,1148.47) 744.93,1117.51 cw(c785.27,1154.4) 730.66,1156.86 730.66,1253.83 cw(c762.05,1251.66) 741.49,1275.48 cw(c766.98,1249.24) 767.57,1285.81 865.81,1285.81 ccw(c857.53,1301.33) 874.36,1296.24
  region net NetJ1_1: 1202.76,522.44 cw(c1209.3,528.99) 1200.04,528.99 1200.04,535.04 1212.6,535.04 1212.6,522.44
  region net NetJ1_1: 1222.44,522.44 ccw(c1215.89,528.99) 1225.15,528.99 1225.15,535.04 1212.6,535.04 1212.6,522.44
  region net NetZ1_2: 1460.7,196.91 1421.34,196.91 1421.34,334.72 1247.72,334.72 1247.72,354.41 1441.02,354.41 1441.02,216.61 1539.44,216.61 1539.44,157.54 1460.7,157.54
  region net NetA2_4: 2062.99,1692.91 2062.99,1791.34 1576.77,1791.34 1576.77,1751.97 2023.62,1751.97 2023.62,1692.91
  region net NetA1_1: 1229.09,78.74 1598.27,78.74 1598.27,98.43 1229.09,98.43
  region net NetA1_1: 1391.34,78.74 1755.75,78.74 1755.75,98.43 1391.34,98.43
  region net VDD_BUCK: 754.28,1127.1 754.28,1164.26 761.17,1171.15 896.02,1171.15 907.83,1159.34 907.83,1130.05 897.98,1120.21 761.17,1120.21
  region net NetL6_1: 803.5,1209.54 803.5,1253.83 807.43,1257.76 882.24,1257.76 897.98,1273.51 899.95,1294.18 906.84,1294.18 907.83,1283.35 907.83,1220.98 893.67,1206.82 806.21,1206.82
  region net GND: 751.33,1179.02 746.81,1183.54 746.81,1253.25 752.32,1258.75 791.69,1258.75 796.61,1253.83 796.61,1206.58 803.5,1199.69 898.97,1199.69 914.72,1215.44 914.72,1274.5 939.32,1274.5 939.32,1246.94 944.24,1242.02 944.24,1199.69 923.57,1179.02
  pour cut-out: 684.57,1510 684.57,1407.73 760.41,1407.73 760.41,1510.04
  region net RF4: 1268.44,204.71 1268.46,157.54 1248.78,137.87 1229.09,157.54 1260.58,196.91 1260.56,204.71
  region net RF1: 1276.31,204.71 1276.31,196.83 1288.14,157.54 1307.83,137.87 1327.51,157.54 1284.19,196.83 1284.19,204.71
  region net RF2: 1276.33,228.41 1276.31,236.2 1291.96,288.39 1327.52,288.39 1327.52,275.67 1284.21,236.18 1284.21,228.41 1276.39,228.41 1276.31,228.33
  region net RF3: 1268.46,228.41 1268.46,295.35 1229.09,295.35 1229.09,275.67 1260.56,236.2 1260.56,228.33
  region net RFC: 1268.44,220.46 1189.72,220.46 1189.72,212.58 1268.44,212.58
  pour cut-out: 1459.45,9.84 1210.9,9.84 1210.9,362.27 1459.45,362.27
  region net GND: 1276.81,221.93 1276.81,211.11 1299.43,211.11 1299.43,228.82 1292.56,228.82 1292.56,221.93
Mid Layer 1:
  rectangle net 1V8_SW: 492.23,713.21 541.12,743.26
  rectangle net 1V8_SW: 492.23,666.14 511.81,743.26
  region net VDD_nRF91: 1090.01,410.05 1009.05,410.05 1009.05,367.51 1090.01,367.51
  region net VBAT_nRF70: 791.42,1343.5 759.93,1343.5 759.93,1276.58 791.42,1276.58
  region net VSYS_SW: 294.78,1525.32 294.78,1441.65 340.06,1441.65 340.06,1525.32
  region net 1V8_SW: 161.42,489.37 161.42,474.1 228.35,474.1 228.35,489.37
  pour cut-out: 1109.92,638.37 1144.32,603.97 cw(c1112.6,572.24) 1157.47,572.24 1157.47,533.86 ccw(c1212.6,533.86) 1267.73,533.86 1267.73,572.24 ccw(c1112.6,572.24) 1222.29,681.94 1187.9,716.34 ccw(c1078.2,606.65) 1080.71,761.76 ccw(c1080.71,706.6) 1080.71,651.44 cw(c1078.2,606.64)
  pour cut-out: 993.8,712.6 1010.29,712.6 ccw(c1010.29,722.68) 1017.42,715.55 1017.42,697.84 ccw(c1010.29,690.71) 1010.29,700.79 993.8,700.79
  pour cut-out: 973.74,846.2 cw(c1001.8,910.04) 957.06,856.55 913.87,890.81 cw(c987.8,875.06) 936.73,930.79 cw(c998.7,868.83) 998.71,956.46 1261.27,956.46 ccw(c1261.27,990.9) 1285.58,966.51 1285.67,966.6 ccw(c1262.79,989.39) 1295.09,989.39 1295.09,1245.98 ccw(c1250.23,1245.99) 1281.94,1277.71 1222.41,1337.24 cw(c1332.11,1446.93) 1176.98,1446.93 1176.98,1487.4 cw(c1232.11,1487.4) 1287.24,1487.4 1287.24,1446.93 ccw(c1332.11,1446.93) 1300.38,1415.21 1359.91,1355.68 cw(c1250.24,1245.99) 1405.35,1245.98 1405.35,989.39 cw(c1262.8,989.38) 1363.59,888.58 cw(c1261.28,990.89) 1261.27,846.2
  pour cut-out: 959.35,833.66 959.35,850.15 ccw(c949.27,850.15) 956.39,857.28 974.11,857.28 ccw(c981.24,850.15) 971.16,850.15 971.16,833.66
  pour cut-out: 952.99,873 ccw(c965.32,869.56) 977.65,866.12 cw(c1001.4,866.12) 984.58,882.89 984.61,882.92 cw(c998.71,868.82) 998.71,888.76 1261.27,888.76 ccw(c1261.27,990.9) 1333.5,918.67 ccw(c1262.78,989.39) 1362.79,989.39 1362.79,1245.98 ccw(c1250.22,1245.98) 1329.82,1325.58 1270.29,1385.11 cw(c1332.11,1446.93) 1244.68,1446.93 1244.68,1487.4 ccw(c1232.11,1487.4) 1219.53,1487.4 1219.53,1446.93 ccw(c1332.11,1446.93) 1252.51,1367.33 1312.04,1307.8 cw(c1250.22,1245.98) 1337.64,1245.98 1337.64,989.39 cw(c1262.79,989.39) 1315.75,936.49 1315.69,936.42 cw(c1261.27,990.9) 1261.27,913.91 998.71,913.91 ccw(c998.71,868.82) 966.83,900.7 ccw(c1001.4,866.12)
  pour cut-out: 692.19,1861.32 cw(c692.19,1874.93) 692.19,1888.54 732.58,1888.54 cw(c732.58,1874.93) 746.19,1874.93 cw(c732.58,1874.93) 732.58,1861.32
  pour cut-out: 771.82,1730.31 771.82,1747.09 cw(c827.73,1747.09) 788.2,1786.62 788.62,1787.04 cw(c818.88,1756.78) 818.88,1799.58 ccw(c818.88,1809.4) 825.8,1802.43 827.16,1803.79 ccw(c803.96,1826.99) 836.77,1826.99 836.77,1858.31 833.99,1861.32 823.92,1861.32 cw(c823.92,1874.93) 823.92,1888.54 833.99,1888.54 cw(c833.99,1858.71) 855.09,1879.8 cw(c833.59,1858.31) 863.99,1858.31 863.99,1826.99 cw(c803.96,1826.99) 846.41,1784.54 845.08,1783.21 cw(c818.88,1809.4) 818.88,1772.36 ccw(c818.88,1756.78) 807.87,1767.8 807.44,1767.37 ccw(c827.73,1747.09) 799.04,1747.09 799.04,1730.31 cw(c785.43,1730.31)
  pour cut-out: 806.1,1681.28 cw(c806.1,1694.88) 806.1,1708.48 918.28,1708.48 cw(c918.28,1646.63) 980.13,1646.63 980.13,1549.21 cw(c966.54,1549.21) 952.94,1549.21 952.94,1646.63 ccw(c918.28,1646.63) 918.28,1681.28
  pour cut-out: 752.15,1641.02 ccw(c765.75,1641.02) 779.35,1641.02 779.35,1698.82 ccw(c765.75,1698.82) 752.15,1698.82
  pour cut-out: 793.1,1610.42 cw(c793.1,1624.02) 793.1,1637.61 899.61,1637.61 cw(c899.61,1588.58) 948.64,1588.58 948.64,1549.21 cw(c935.04,1549.21) 921.44,1549.21 921.44,1588.58 ccw(c899.61,1588.58) 899.61,1610.42
  pour cut-out: 630.25,1261.74 ccw(c689.05,1261.74) 689.05,1202.94 711.61,1202.94 ccw(c711.61,1216.54) 725.21,1216.54 ccw(c711.61,1216.54) 711.61,1230.13 689.05,1230.13 cw(c689.05,1261.74) 657.44,1261.74 657.44,1577.85 cw(c690.01,1577.85) 690.01,1610.42 738.45,1610.42 ccw(c738.45,1624.02) 752.05,1624.02 ccw(c738.45,1624.02) 738.45,1637.61 690.01,1637.61 ccw(c690.01,1577.85) 630.25,1577.85
  pour cut-out: 874.36,1317.8 883.22,1317.8 883.22,1294.65 cw(c863.07,1294.65) 877.32,1280.4 cw(c865.44,1292.27) 865.43,1275.48 773.12,1275.48 ccw(c773.11,1241.91) 749.36,1265.64 ccw(c768.32,1246.65) 741.49,1246.63 741.49,1143.9 ccw(c768.33,1143.88) 749.36,1124.89 ccw(c775.49,1151) 775.5,1114.06 899.17,1114.06 ccw(c899.17,1161.09) 932.43,1127.84 ccw(c854.67,1186.05) 950.15,1168.2 950.15,1317.8 960.98,1317.8 960.98,1186.5 cw(c865.1,1177.4) 939.32,1116.03 cw(c905.01,1144.96) 908.81,1100.24 777.76,1100.24 cw(c782.19,1148.5) 744.93,1117.51 cw(c785.29,1154.41) 730.66,1156.86 730.66,1253.83 cw(c762.05,1251.66) 741.49,1275.48 cw(c766.98,1249.24) 767.57,1285.81 865.81,1285.81 ccw(c857.5,1301.35) 874.36,1296.24
  region net VDD_BUCK: 925.71,1136.42 925.71,1153.15 ccw(c918.82,1153.15) 918.82,1160.04 901.1,1160.04 ccw(c901.1,1153.15) 894.21,1153.15 894.21,1136.42 ccw(c901.1,1136.42) 901.1,1129.53 918.82,1129.53 ccw(c918.82,1136.42)
  pour cut-out: 1150.74,444.3 ccw(c1189.72,405.31) 1228.71,366.33 1242.29,379.91 ccw(c1180.85,441.34) 1267.73,441.34 ccw(c1212.6,441.34) 1158.52,452.08
  pour cut-out: 1167.09,212.07 1167.09,217.35 ccw(c1109.95,217.35) 1150.35,257.76 cw(c1188.41,295.81) 1134.59,295.81 1134.59,301.06 1189.74,301.06 1189.74,212.07
  pour cut-out: 1212.39,212.07 1212.39,217.35 cw(c1269.52,217.35) 1229.12,257.76 ccw(c1191.07,295.81) 1244.88,295.81 1244.88,301.06 1189.74,301.06 1189.74,212.07
  pour cut-out: 1244.86,406.5 1244.86,293.31 cw(c1189.72,293.31) 1134.59,293.31 1134.59,406.5
  pour cut-out: 1222.59,1337.24 1282.12,1277.71 cw(c1250.4,1245.98) 1295.26,1245.98 ccw(c1350.39,1245.98) 1405.53,1245.98 ccw(c1250.4,1245.98) 1360.09,1355.68 1300.56,1415.21 cw(c1332.28,1446.93) 1287.42,1446.93 1287.42,1545.53 ccw(c1232.28,1545.53) 1177.15,1545.53 1177.15,1446.93 ccw(c1332.28,1446.93)
  pour cut-out: 1462.6,1826.79 1327.17,1826.79 ccw(c1327.17,1771.65) 1287.98,1810.44 ccw(c1326.77,1771.26) 1271.64,1771.26 1271.64,1728.74 ccw(c1326.77,1728.74) 1326.77,1673.61 ccw(c1326.77,1728.74) 1380.53,1716.52 1462.6,1716.52 ccw(c1462.6,1771.65)
  pour cut-out: 1271.64,1635.83 1271.64,1771.26 cw(c1326.77,1771.26) 1287.98,1810.44 cw(c1327.17,1771.65) 1327.17,1826.79 1369.68,1826.79 cw(c1369.68,1771.65) 1424.82,1771.65 cw(c1369.68,1771.65) 1381.9,1717.89 1381.9,1635.83 cw(c1326.77,1635.83)
  pour cut-out: 762.14,1030.64 722.26,1030.64 722.26,983.41 762.14,983.41
  pour cut-out: 932.68,1085.56 892.8,1085.56 892.8,1038.32 932.68,1038.32
  pour cut-out: 1017.42,697.84 1053.84,651.58 1133.43,651.58 1074.57,761.81 1053.84,761.81 1017.42,715.55
  pour cut-out: 749.74,273.04 749.74,312.92 702.5,312.92 702.5,273.04
  pour cut-out: 237.59,1808.31 277.48,1808.31 277.48,1855.39 237.59,1855.39
  pour cut-out: 218.33,597.6 265.52,597.6 265.52,683.64 218.33,683.64
  pour cut-out: 921.44,1549.21 921.44,1505.17 980.13,1505.17 980.13,1549.21
  pour cut-out: 718.51,1610.42 814.21,1610.42 814.21,1772.64 718.51,1772.64
  pour cut-out: 1459.45,9.84 1210.9,9.84 1210.9,330.17 1459.45,330.17
  pour cut-out: 1260.6,204.71 1260.6,196.83 1234.61,170.84 1234.61,130.09 1262.56,130.09 1262.56,154.1 1268.48,160.02 1268.48,204.71
  pour cut-out: 1284.23,204.71 1284.23,196.83 1310.22,170.84 1310.22,130.09 1282.27,130.09 1282.27,154.1 1276.35,160.02 1276.35,204.71
  pour cut-out: 1318.86,162.33 1284.23,204.71 1260.6,204.71 1225.94,162.35
  pour cut-out: 1318.86,270.71 1284.23,228.33 1260.6,228.33 1225.94,270.68
  pour cut-out: 1260.6,228.33 1260.6,236.2 1234.61,262.2 1234.61,302.95 1262.56,302.95 1262.56,278.94 1268.48,273.02 1268.48,228.33
  pour cut-out: 1284.23,228.33 1284.23,236.2 1310.22,262.2 1310.22,302.95 1282.27,302.95 1282.27,278.94 1276.35,273.02 1276.35,228.33
  pour cut-out: 1513.78,143.44 1243.7,143.44 1243.7,33.21 1513.78,33.21
  pour cut-out: 1513.78,399.59 1243.7,399.59 1243.7,289.35 1513.78,289.35
  pour cut-out: 1393.83,141.84 1393.83,399.59 1504.06,399.59 1504.06,141.84
  pour cut-out: 1478.94,197.33 1439.6,197.33 1439.6,335.13 1252.36,335.13 1252.36,353.82 1458.29,353.82 1458.29,216.02 1556.71,216.02 1556.71,157.96 1478.94,157.96
  pour cut-out: 1203.74,583.58 1157.48,547.16 1157.48,440.86 1267.71,440.86 1267.71,547.16 1221.45,583.58
  pour cut-out: 1391.34,78.74 1755.75,78.74 1755.75,97.91 1391.34,97.91
Mid Layer 2:
  rectangle net VDD_nRF91: 1009,367.51 1044.81,410.05
  rectangle net VBAT_nRF70: 399.61,1245.08 460.63,1264.76
  region net VBAT_nRF70: 759.84,1343.5 759.84,1309.06 791.34,1309.06 791.34,1343.5
  region net 1V8_SW: 161.42,489.37 161.42,474.1 228.35,474.1 228.35,489.37
  rectangle net VDD_nRF91: 505.91,530.51 588.58,573.06
  pour cut-out: 959.35,833.66 959.35,850.15 ccw(c949.27,850.15) 956.39,857.28 974.11,857.28 ccw(c981.24,850.15) 971.16,850.15 971.16,833.66
  pour cut-out: 993.8,712.6 1010.29,712.6 ccw(c1010.29,722.68) 1017.42,715.55 1017.42,697.84 ccw(c1010.29,690.71) 1010.29,700.79 993.8,700.79
  pour cut-out: 1109.92,638.37 1144.32,603.97 cw(c1112.6,572.24) 1157.47,572.24 1157.47,533.86 ccw(c1212.6,533.86) 1267.73,533.86 1267.73,572.24 ccw(c1112.6,572.24) 1222.29,681.94 1187.9,716.34 ccw(c1078.2,606.65) 1080.71,761.76 ccw(c1080.71,706.6) 1080.71,651.44 cw(c1078.2,606.64)
  pour cut-out: 973.74,846.2 cw(c1001.8,910.04) 957.06,856.55 913.87,890.81 cw(c987.8,875.06) 936.73,930.79 cw(c998.7,868.83) 998.71,956.46 1261.27,956.46 ccw(c1261.27,990.9) 1285.58,966.51 1285.67,966.6 ccw(c1262.79,989.39) 1295.09,989.39 1295.09,1245.98 ccw(c1250.23,1245.99) 1281.94,1277.71 1222.41,1337.24 cw(c1332.11,1446.93) 1176.98,1446.93 1176.98,1487.4 cw(c1232.11,1487.4) 1287.24,1487.4 1287.24,1446.93 ccw(c1332.11,1446.93) 1300.38,1415.21 1359.91,1355.68 cw(c1250.24,1245.99) 1405.35,1245.98 1405.35,989.39 cw(c1262.8,989.38) 1363.59,888.58 cw(c1261.28,990.89) 1261.27,846.2
  pour cut-out: 1462.6,1826.79 1327.17,1826.79 ccw(c1327.17,1771.65) 1287.98,1810.44 ccw(c1326.77,1771.26) 1271.64,1771.26 1271.64,1728.74 ccw(c1326.77,1728.74) 1326.77,1673.61 ccw(c1326.77,1728.74) 1380.53,1716.52 1462.6,1716.52 ccw(c1462.6,1771.65)
  pour cut-out: 1271.64,1635.83 1271.64,1771.26 cw(c1326.77,1771.26) 1287.98,1810.44 cw(c1327.17,1771.65) 1327.17,1826.79 1369.68,1826.79 cw(c1369.68,1771.65) 1424.82,1771.65 cw(c1369.68,1771.65) 1381.9,1717.89 1381.9,1635.83 cw(c1326.77,1635.83)
  pour cut-out: 1222.59,1337.24 1282.12,1277.71 cw(c1250.4,1245.98) 1295.26,1245.98 ccw(c1350.39,1245.98) 1405.53,1245.98 ccw(c1250.4,1245.98) 1360.09,1355.68 1300.56,1415.21 cw(c1332.28,1446.93) 1287.42,1446.93 1287.42,1545.53 ccw(c1232.28,1545.53) 1177.15,1545.53 1177.15,1446.93 ccw(c1332.28,1446.93)
  pour cut-out: 1167.09,212.07 1167.09,217.35 ccw(c1109.95,217.35) 1150.35,257.76 cw(c1188.41,295.81) 1134.59,295.81 1134.59,301.06 1189.74,301.06 1189.74,212.07
  pour cut-out: 1212.39,212.07 1212.39,217.35 cw(c1269.52,217.35) 1229.12,257.76 ccw(c1191.07,295.81) 1244.88,295.81 1244.88,301.06 1189.74,301.06 1189.74,212.07
  pour cut-out: 1244.86,406.5 1244.86,293.31 cw(c1189.72,293.31) 1134.59,293.31 1134.59,406.5
  pour cut-out: 1150.74,444.3 ccw(c1189.72,405.31) 1228.71,366.33 1242.29,379.91 ccw(c1180.85,441.34) 1267.73,441.34 ccw(c1212.6,441.34) 1158.52,452.08
  region net VDD_BUCK: 925.71,1153.15 ccw(c918.82,1153.15) 918.82,1160.04 ccw(c918.82,1153.15) 911.93,1153.15 911.93,1136.42 ccw(c918.82,1136.42) 918.82,1129.53 ccw(c918.82,1136.42) 925.71,1136.42
  pour cut-out: 762.14,1030.64 722.26,1030.64 722.26,983.41 762.14,983.41
  pour cut-out: 932.68,1085.56 892.8,1085.56 892.8,1038.32 932.68,1038.32
  pour cut-out: 1017.42,697.84 1053.84,651.58 1133.43,651.58 1074.57,761.81 1053.84,761.81 1017.42,715.55
  pour cut-out: 749.74,273.04 749.74,312.92 702.5,312.92 702.5,273.04
  pour cut-out: 237.59,1808.31 277.48,1808.31 277.48,1855.39 237.59,1855.39
  pour cut-out: 218.33,597.6 265.52,597.6 265.52,683.64 218.33,683.64
  pour cut-out: 1495.28,399.59 1225.2,399.59 1225.2,289.35 1495.28,289.35
  pour cut-out: 1393.83,141.84 1393.83,399.59 1504.06,399.59 1504.06,141.84
  pour cut-out: 1478.94,197.33 1439.6,197.33 1439.6,335.13 1252.36,335.13 1252.36,353.82 1458.29,353.82 1458.29,216.02 1556.71,216.02 1556.71,157.96 1478.94,157.96
  pour cut-out: 1459.45,9.84 1210.9,9.84 1210.9,330.17 1459.45,330.17
  pour cut-out: 1513.78,143.44 1243.7,143.44 1243.7,33.21 1513.78,33.21
  pour cut-out: 1284.23,204.71 1284.23,196.83 1310.22,170.84 1310.22,130.09 1282.27,130.09 1282.27,154.1 1276.35,160.02 1276.35,204.71
  pour cut-out: 1318.86,162.33 1284.23,204.71 1260.6,204.71 1225.94,162.35
  pour cut-out: 1260.6,204.71 1260.6,196.83 1234.61,170.84 1234.61,130.09 1262.56,130.09 1262.56,154.1 1268.48,160.02 1268.48,204.71
  pour cut-out: 1318.86,270.71 1284.23,228.33 1260.6,228.33 1225.94,270.68
  pour cut-out: 1284.23,228.33 1284.23,236.2 1310.22,262.2 1310.22,302.95 1282.27,302.95 1282.27,278.94 1276.35,273.02 1276.35,228.33
  pour cut-out: 1260.6,228.33 1260.6,236.2 1234.61,262.2 1234.61,302.95 1262.56,302.95 1262.56,278.94 1268.48,273.02 1268.48,228.33
  pour cut-out: 1203.74,583.58 1157.48,547.16 1157.48,440.86 1267.71,440.86 1267.71,547.16 1221.45,583.58
  pour cut-out: 1409.84,78.74 1774.25,78.74 1774.25,97.91 1409.84,97.91
Mid Layer 3:
  rectangle net 3V3: 882.91,1539.25 907.15,1568.58
  rectangle net VBAT_nRF70: 384.84,1244.09 449.8,1270.67
  region net 1V8_SW: 492.13,753.34 492.13,687.39 511.81,687.39 511.81,753.34
  region net VDD_nRF53: 460.63,754.32 460.63,688.38 480.31,688.38 480.31,754.32
  region net 3V3: 365.16,573.82 365.16,512.8 384.84,512.8 384.84,573.82
  region net VSYS_SW: 297.74,1525.31 297.74,1438.98 337.11,1438.98 337.11,1525.31
  rectangle net VSYS_SW: 503.94,1378.94 571.34,1418.31
  region net VBAT_nRF70: 375.98,1248.03 356.3,1248.03 356.3,1187.99 375.98,1187.99
  region net VBUS: 199.8,1527.56 199.8,1507.87 272.63,1507.87 272.63,1527.56
  rectangle net VBUS_CONN: 289.37,1100.39 322.83,1229.33
  region net VBUS: 288.64,1662.4 288.64,1696.85 224.41,1696.85 224.41,1662.4
  region net VOUT_BUCK3: 253.94,238.19 253.94,257.87 187.01,257.87 187.01,238.19
  region net VBAT_nRF70: 253.94,269.68 253.94,289.37 187.01,289.37 187.01,269.68
  region net VDD_nRF53: 247.05,332.68 247.05,352.36 187.01,352.36 187.01,332.68
  region net 1V8_SW: 247.05,301.18 247.05,320.87 187.01,320.87 187.01,301.18
  region net GND: 990.84,712.6 1010.29,712.6 ccw(c1010.29,722.68) 1017.42,715.55 1017.42,697.84 ccw(c1010.29,690.71) 1010.29,700.79 990.84,700.79
  region net VDD_SENS: 830.71,1695.87 851.38,1695.87 cw(c851.38,1686.02) 861.22,1686.02 cw(c851.38,1686.02) 851.38,1676.18 830.71,1676.18
  region net GND: 1222.59,1337.24 1282.12,1277.71 cw(c1250.4,1245.98) 1295.26,1245.98 ccw(c1350.39,1245.98) 1405.53,1245.98 ccw(c1250.4,1245.98) 1360.09,1355.68 1300.56,1415.21 cw(c1332.28,1446.93) 1287.42,1446.93 1287.42,1545.53 ccw(c1232.28,1545.53) 1177.15,1545.53 1177.15,1446.93 ccw(c1332.28,1446.93)
  region net GND: 1212.39,212.07 1212.39,217.35 cw(c1269.52,217.35) 1229.12,257.76 ccw(c1191.07,295.81) 1244.88,295.81 1244.88,301.06 1189.74,301.06 1189.74,212.07
  region net GND: 1150.74,444.3 ccw(c1189.72,405.31) 1228.71,366.33 1242.29,379.91 ccw(c1180.85,441.34) 1267.73,441.34 ccw(c1212.6,441.34) 1158.52,452.08
  region net GND: 1244.86,406.5 1244.86,293.31 cw(c1189.72,293.31) 1134.59,293.31 1134.59,406.5
  region net GND: 1167.09,212.07 1167.09,217.35 ccw(c1109.95,217.35) 1150.35,257.76 cw(c1188.41,295.81) 1134.59,295.81 1134.59,301.06 1189.74,301.06 1189.74,212.07
  region net VOUT_BUCK3: 329.73,1304.46 338.65,1313.39 359.32,1313.39 cw(c359.32,1305.51) 367.2,1305.51 367.2,1286.81 345.54,1265.16 329.72,1265.16
  region net VBAT_nRF70: 356.3,1248.03 356.3,1257.87 369.09,1270.67 389.76,1270.67 cw(c389.76,1262.8) 397.64,1262.8 397.64,1244.09 375.98,1222.44 356.3,1222.44
  region net 3V3: 887.21,1568.58 877.35,1568.58 863.48,1554.7 863.48,1542.71 866.94,1539.25 871.46,1539.25 887.21,1539.25
  region net GND: 1284.23,228.33 1284.23,236.2 1310.22,262.2 1310.22,302.95 1282.27,302.95 1282.27,278.94 1276.35,273.02 1276.35,228.33
  region net GND: 1260.6,228.33 1260.6,236.2 1234.61,262.2 1234.61,302.95 1262.56,302.95 1262.56,278.94 1268.48,273.02 1268.48,228.33
  region net GND: 1318.86,270.71 1284.23,228.33 1260.6,228.33 1225.94,270.68
  region net GND: 1318.86,162.33 1284.23,204.71 1260.6,204.71 1225.94,162.35
  region net GND: 1284.23,204.71 1284.23,196.83 1310.22,170.84 1310.22,130.09 1282.27,130.09 1282.27,154.1 1276.35,160.02 1276.35,204.71
  region net GND: 1260.6,204.71 1260.6,196.83 1234.61,170.84 1234.61,130.09 1262.56,130.09 1262.56,154.1 1268.48,160.02 1268.48,204.71
  region net VBUS_CONN: 322.83,1225.73 322.83,1271.65 309.06,1285.43 247.05,1285.43 247.05,1271.65 289.37,1229.33
  region net VBUS: 272.63,1527.49 219.41,1580.71 199.93,1580.71 199.93,1524.73 200.79,1525.59 272.63,1525.59
  region net NetC9_2: 590.55,1687.01 590.55,1597.44 524.61,1531.5 275.59,1531.5 224.41,1582.68 224.41,1629.92 313.98,1629.92 313.98,1595.47 342.52,1566.93 505.91,1566.93 550.92,1611.95 550.92,1687.01
  pour cut-out: 1446.85,1902.02 1663.39,1902.02 1663.39,2095.62 1446.85,2095.62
